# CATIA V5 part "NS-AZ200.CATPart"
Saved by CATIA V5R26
Part number: NS-AZ200
Bounding box of the stored display mesh (mm): x -120.6 to 15, y -220 to -60, z -55.6 to 55.6
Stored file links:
  R:\Document\坂尻\その他\ナベヤデータ変換\安全カバーキャスター\NS-AZ\NS-AZ200.CATPart
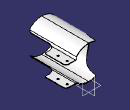
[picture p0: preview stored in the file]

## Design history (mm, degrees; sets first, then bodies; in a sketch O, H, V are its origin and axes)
Body1 (main body)
Body2 "ﾎﾞﾃﾞｨｰ.1"
  Solid1: solid without history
